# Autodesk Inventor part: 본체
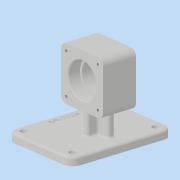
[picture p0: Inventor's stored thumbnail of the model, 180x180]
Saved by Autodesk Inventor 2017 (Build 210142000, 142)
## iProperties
Part Number: 본체
Material: 일반
Document SubType Name: Modeling
Designer: 222
Density: 1 g/cm^3
Appearance: 기본값
Author: 222
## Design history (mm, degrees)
sketch "스케치1"
  geometry: L1 (-32, 32)-(32, 32); L2 (32, 32)-(32, -32); L3 (32, -32)-(-32, -32); L4 (-32, -32)-(-32, 32); L5 (-32, 32)-(32, -32); L6 (32, 32)-(-32, -32); 1 further point
  constraints: 12 end point, 2 midpoint, 2 parallel, 1 horizontal, 1 perpendicular
  dimensions: "d0" = 64 distance of L2.end L3.end; "d1" = 64 distance of L1.end L2.end
extrude "돌출1" new body sketch "스케치1" stored distance "d2" = 42; taper "d3" = 0 deg
sketch "스케치2"
  geometry: C1 r 21 at (0, 0); 1 further point
  constraints: 1 centre point, 1 coincident
  dimensions: "d4" = 42 diameter of C1
extrude "돌출2" cut sketch "스케치2" distance "d5" = 15; taper "d6" = 0 deg
sketch "스케치3"
  geometry: C1 r 18 at (0, 0); 1 further point
  constraints: 1 centre point, 1 coincident
  dimensions: "d7" = 36 diameter of C1
extrude "돌출3" cut sketch "스케치3" distance "d8" = 15; taper "d9" = 0 deg
fillet "모깎기1" dims "d10" = 8
hole "구멍1" diameter "d13" = 3.242; stored, may be unused: countersink angle "d17" = 90 deg, drill point angle "d19" = 118 deg; dims "d11" = 10, "d12" = 10, "d14" = 8, "d15" = 4, "d16" = 2, "d18" = 10
node "작업 평면1"
sketch "스케치4"
  geometry: L1 (36, 65)-(-62, 65); L2 (-62, 65)-(-62, -65); L3 (-62, -65)-(36, -65); L4 (36, -65)-(36, 65); 1 further point
  constraints: 8 end point, 2 parallel, 1 horizontal, 1 perpendicular
  dimensions: "d21" = 130 distance of L3.end L1.start; "d22" = 98 distance of L2.end L3.end; "d23" = 65 distance from line of point (0, 0) L3; "d25" = 62 distance from line of L2 point (0, 0)
extrude "돌출4" join sketch "스케치4" distance "d26" = 10; taper "d27" = 0 deg
sketch "스케치5"
  geometry: L1 (24, -32)-(-24, -32) reference; L2 (36, -60)-(-62, -60) reference; L3 (-20, -32)-(-20, -60); L4 (20, -32)-(20, -60); 1 further point
  constraints: 4 end point, 4 point on line, 2 vertical
  dimensions: "d28" = 40 distance between parallel lines of L4 L3; "d29" = 20 distance from line of point (0, 0) L3
extrude "돌출5" join sketch "스케치5" stored distance "d30" = 8; taper "d31" = 0 deg
sketch "스케치6"
  geometry: L1 (-32, -21)-(-32, 21) reference; L2 (-32, 4)-(-60, 4) reference; L3 (-60, -4)-(-32, -4) reference; L4 (-60, -65)-(-60, 65) reference; L5 (-32, 17)-(-60, 17); L6 (-32, -17)-(-60, -17); 1 further point
  constraints: 4 end point, 4 point on line, 2 horizontal
  dimensions: "d32" = 34 distance between parallel lines of L6 L5; "d33" = 17 distance from line of point (0, 0) L5
extrude "돌출6" join sketch "스케치6" stored distance "d34" = 8; taper "d35" = 0 deg
fillet "모깎기2" dims "d36" = 12
hole "구멍2" diameter "d39" = 9; stored, may be unused: countersink angle "d43" = 90 deg, drill point angle "d45" = 118 deg; dims "d37" = 10, "d38" = 10, "d40" = 8, "d41" = 4, "d42" = 2, "d44" = 10
node "작업 평면2"
fillet "모깎기3" dims "d46" = 3
fillet "모깎기4" dims "d47" = 3
fillet "모깎기5" dims "d48" = 0.3
chamfer "모따기1" distance "d49" = 1; stored, may be unused: second distance "d50" = 2, angle "d51" = 45 deg
sketch "스케치7"
  geometry: L1 (-62, 53)-(-62, -53) reference; 2 further points
  constraints: 1 horizontal alignment, 1 other
  dimensions: "d52" = 10 distance from line of point (-52, 0) L1
feature "엠보싱1" sketch "스케치7" dims "d0" = 64, "d1" = 64, "d53" = 0.5, "d54" = 0
node "솔리드1"
mirror "미러1"
mirror "미러2"
mirror "미러3"
mirror "미러4"
mirror "미러5"
